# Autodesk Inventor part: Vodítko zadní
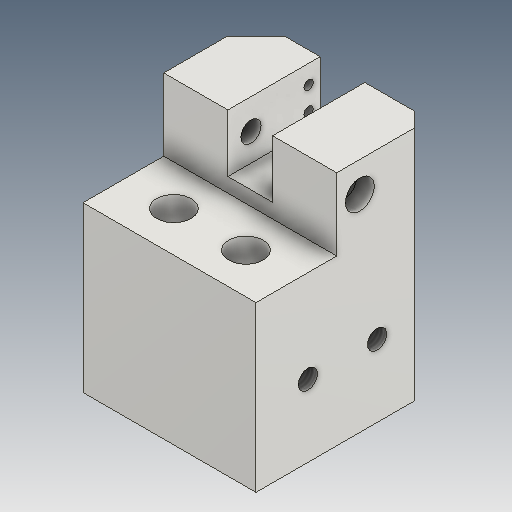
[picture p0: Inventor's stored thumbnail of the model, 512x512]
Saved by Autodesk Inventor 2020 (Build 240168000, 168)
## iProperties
Created: 2025-03
Part Number: Vodítko zadní
Material: Ocel
Document SubType Name: Modeling
Designer: doma
Density: 7.85 g/cm^3
Appearance: Ocel
Mass: 1726.66 g
Surface Area: 323.011 cm^2
Volume: 219.956 cm^3
Author: doma
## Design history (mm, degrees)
sketch "Náčrt1"
  geometry: L1 (0, 0)-(60, 0); L2 (60, 0)-(60, 82); L3 (0, 82)-(0, 0); L4 (30, 62)-(37.75, 62); L5 (30, 62)-(22.25, 62); L6 (22.25, 62)-(22.25, 82); L7 (37.75, 62)-(37.75, 82); L8 (60, 82)-(37.75, 82); L9 (22.25, 82)-(0, 82)
  constraints: 18 end point, 3 horizontal, 3 parallel, 3 perpendicular, 1 vertical
  dimensions: "d0" = 60 distance of L3.start L2.end; "d1" = 82 distance of L2.end L1.end
extrude "Vysunutí1" new body sketch "Náčrt1" distance "d5" = 60; taper "d6" = 0 deg
sketch "Náčrt2"
  geometry: L1 (22.25, 82)-(0, 82) reference; L2 (60, 0)-(60, 82) reference; L3 (0, 82)-(60, 82); L4 (60, 82)-(60, 57); L5 (60, 57)-(0, 57); L6 (0, 57)-(0, 82); 3 further points
  constraints: 8 end point, 2 parallel, 1 horizontal, 1 perpendicular, 1 point on line
  dimensions: "d7" = 25 distance of L3.end L4.end
extrude "Vysunutí2" cut sketch "Náčrt2" distance "d8" = 28; taper "d9" = 0 deg
sketch "Náčrt3"
  geometry: L1 (0, 0)-(60, 0) reference; L2 (60, 0)-(60, 60) reference; L3 (0, 60)-(60, 60) reference; L4 (0, 0)-(0, 60) reference; L5 (0, 32)-(22.25, 32) reference; L6 (22.25, 0)-(22.25, 32) reference; L7 (37.75, 0)-(37.75, 32) reference; L8 (60, 32)-(60, 60) reference; L9 (60, 46)-(0, 46); L10 (0, 60)-(0, 32) reference; 3 further points
  constraints: 2 end point, 2 midpoint, 2 point on line, 1 horizontal
  dimensions: "d10" = 25 distance of point (17.5, 46) point (42.5, 46); "d11" = 17.5 distance from line of L4 point (17.5, 46); "d12" = 14 distance between parallel lines of L5 L9
hole "Díra1" sketch "Náčrt3" at (42.5, 46), (17.5, 46) diameter "d13" = 9; stored, may be unused: countersink angle "d17" = 90 deg, drill point angle "d19" = 118 deg; dims "d14" = 5, "d15" = 14, "d16" = 8, "d18" = 8
sketch "Náčrt4"
  geometry: C1 r 6 at (42.5, 14); C2 r 6 at (17.5, 14); 3 further points
  constraints: 2 centre point, 2 coincident
  dimensions: "d20" = 12 diameter of C1; "d21" = 12 diameter of C2
extrude "Vysunutí3" cut sketch "Náčrt4" distance "d22" = 30; taper "d23" = 0 deg
sketch "Náčrt5"
  geometry: L1 (15.5, 0)-(0, 0) reference; L2 (7.75, 0)-(7.75, -32); L3 (0, -32)-(15.5, -32) reference; C1 r 6 at (7.75, -15); 1 further point
  constraints: 2 end point, 2 midpoint, 1 centre point, 1 point on line
  dimensions: "d24" = 12 diameter of C1; "d72" = 15 distance from line of L1 C1.centre
extrude "Vysunutí4" cut sketch "Náčrt5" distance "d25" = 2; taper "d26" = 0 deg
chamfer "Zkosení1" distance "d27" = 10; stored, may be unused: second distance "d28" = 2, angle "d29" = 45 deg
sketch "Náčrt6"
  geometry: L1 (-14, 20)-(-14, 31) reference; L2 (-25, 20)-(-25, 31) reference; L3 (-38, 20)-(-38, 31) reference; L4 (-22, 31)-(-22, 20) reference; L5 (-46, 31)-(-46, 20) reference; L6 (-50, 0)-(0, 0) reference; A1 r 4 centre (-18, 20) between (-22, 20) and (-14, 20) reference; A2 r 4 centre (-18, 31) between (-14, 31) and (-22, 31) reference; A3 r 4 centre (-42, 20) between (-46, 20) and (-38, 20) reference; A4 r 4 centre (-42, 31) between (-38, 31) and (-46, 31) reference; 3 further points
  dimensions: "d33" = 25 distance from line of L6 point (-18, 25); "d34" = 25 distance from line of L6 point (-42, 25)
hole "Díra2" sketch "Náčrt6" at (-18, 25), (-42, 25) diameter "d35" = 6.647; stored, may be unused: countersink angle "d39" = 90 deg, drill point angle "d41" = 118 deg; dims "d36" = 8, "d37" = 4, "d38" = 2, "d40" = 10
sketch "Náčrt7"
  geometry: L1 (-50, 82)-(-28, 82) reference; L2 (-28, 57)-(-28, 82) reference; 2 further points
  dimensions: "d42" = 10.5 distance from line of L1 point (-36, 71.5); "d43" = 8 distance from line of L2 point (-36, 71.5)
hole "Díra3" sketch "Náčrt7" at (-36, 71.5) diameter "d44" = 7; stored, may be unused: countersink angle "d48" = 90 deg, drill point angle "d50" = 118 deg; dims "d45" = 5, "d46" = 10, "d47" = 6, "d49" = 27.45
node "Pracovní rovina1"
mirror "Zrcadlit1"
sketch "Náčrt8"
  geometry: L1 (-4, 67.5)-(-4, 75.5); L2 (0, 82)-(-32, 82) reference; L3 (0, 0)-(0, 82) reference
  constraints: 2 end point, 1 vertical
  dimensions: "d51" = 8 distance of L1.start L1.end; "d52" = 6.5 distance from line of L2 L1.end; "d53" = 4 distance from line of L3 L1.end
hole "Díra4" sketch "Náčrt8" at (-4, 75.5), (-4, 67.5) diameter "d54" = 3.242; stored, may be unused: countersink angle "d58" = 90 deg, drill point angle "d60" = 118 deg; dims "d55" = 24, "d56" = 10, "d57" = 6, "d59" = 29.8
chamfer "Zkosení3" distance "d61" = 5; stored, may be unused: second distance "d62" = 2, angle "d63" = 45 deg
sketch "Náčrt9"
  geometry: L1 (0, 0)-(60, 0) reference; L2 (30, 0)-(30, -60); L3 (37.75, -60)-(22.25, -60) reference; 2 further points
  constraints: 2 end point, 2 midpoint, 1 point on line
  dimensions: "d64" = 10 distance from line of L3 point (30, -50)
hole "Díra5" sketch "Náčrt9" at (30, -50) diameter "d65" = 8.376; stored, may be unused: countersink angle "d69" = 90 deg, drill point angle "d71" = 118 deg; dims "d66" = 10, "d67" = 10, "d68" = 6, "d70" = 55
chamfer "Zkosení4" distance "d74" = 1; stored, may be unused: second distance "d75" = 2, angle "d76" = 45 deg
sketch "Náčrt10"
  geometry: L1 (-60, 0)-(-60, 82) reference; L2 (-60, 62)-(-55, 57); L3 (-55, 82)-(-55, 0) reference; L4 (-60, 82)-(-28, 82) reference; L5 (-59, 62)-(-28, 62) reference; L6 (-60.707, 61.293)-(-55.707, 56.293); L7 (-55.707, 56.293)-(-55, 57); L8 (-60.707, 61.293)-(-60, 62)
  constraints: 8 end point, 2 parallel, 2 point on line
  dimensions: "d73" = 20 distance from line of L2.start L4; "d77" = 135 deg angle of L5 L2; "d78" = 1 distance between parallel lines of L2 L6
revolve "Rotace1" sketch "Náčrt10" stored, may be unused: angle "d79" = 90 deg
mirror "Zrcadlit2"
node "Upravit přímo1"
node "Těleso1"
node "Promítnutá smyčka1"
node "Referenční1"
node "Referenční2"
node "Referenční3"
node "Referenční4"
node "Referenční5"
node "Referenční6"
node "Referenční7"
node "Referenční8"
node "Referenční9"
feature "Odstranit1"
